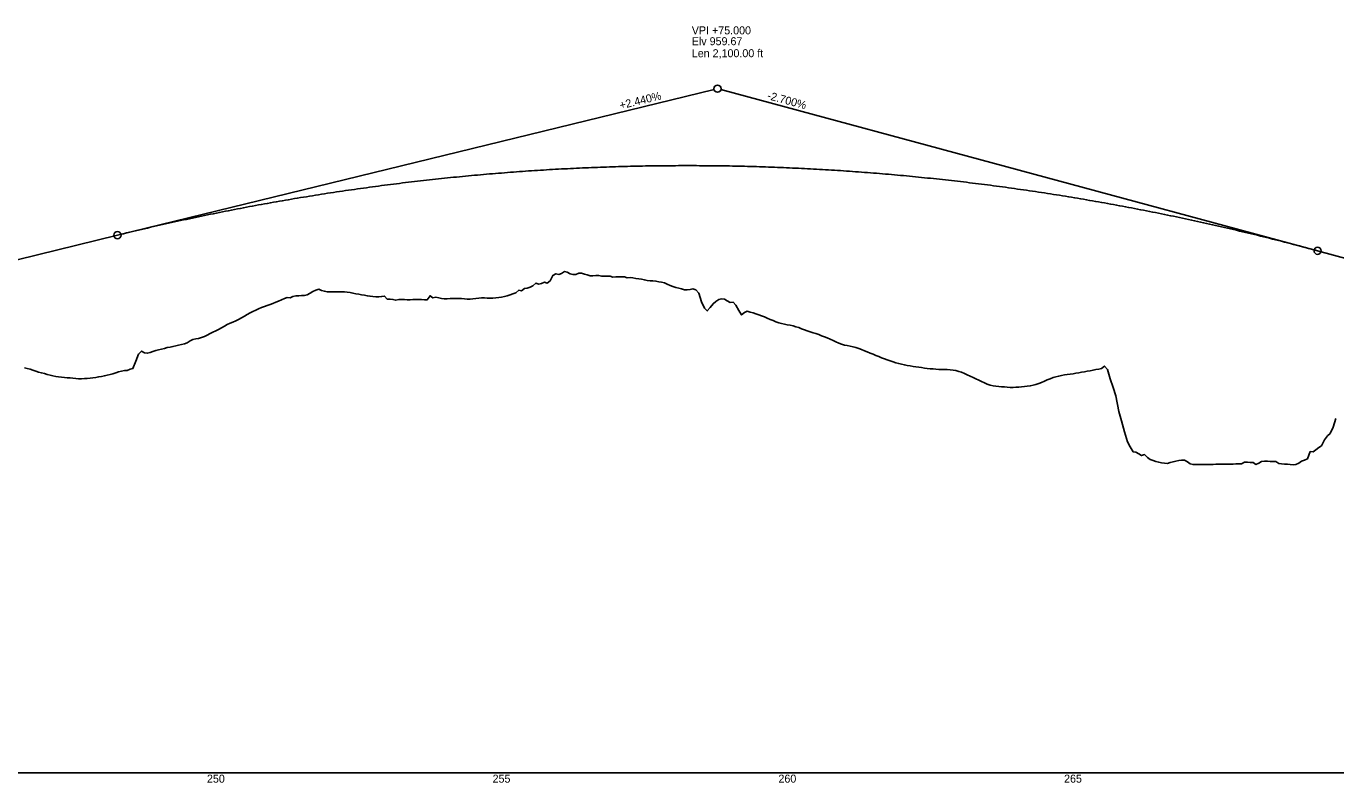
# Model space of a CAD drawing. Extents: x 5180909 to 5237144, y 3695282 to 3720102.
# Drawn here: x 5228426 to 5230717, y 3697765 to 3699088 of the extents above; entities that cross this region are included whole.
import ezdxf

# ---------------------------------------------------------------- set-up
doc = ezdxf.new("R2010")
doc.units = 0
for name, color, linetype in [('dsnEntranceGranular', 7, 'Continuous'), ('dsnShoulderGran', 7, 'Continuous'), ('dsnShoulderPaved', 7, 'Continuous'), ('dsnStgShadingPropGrdLim', 7, 'Continuous'), ('EdgeShoulder', 7, 'Continuous'), ('Entrance', 7, 'Continuous')]:
    doc.layers.add(name, color=color, linetype=linetype)

msp = doc.modelspace()

# ---------------------------------------------------------------- linework, layer by layer
at = {"layer": 'dsnEntranceGranular'}
msp.add_line((5221643.6, 3697782), (5237143.6, 3697782), dxfattribs=at)
at = {"layer": 'dsnShoulderPaved'}
for points in [[(5229142.7, 3698614.1), (5229147.7, 3698613), (5229152.7, 3698611.9), (5229157.7, 3698611), (5229162.7, 3698611.1), (5229167.7, 3698611.4), (5229172.7, 3698611.4), (5229177.7, 3698611.5), (5229182.7, 3698611.8), (5229187.7, 3698611.7), (5229192.7, 3698611.1), (5229197.7, 3698610.7), (5229202.7, 3698610.7), (5229207.7, 3698611.1), (5229212.7, 3698611.7), (5229217.7, 3698612.3), (5229222.7, 3698612.9), (5229227.7, 3698612.7), (5229232.7, 3698612.4), (5229237.7, 3698612.1), (5229242.7, 3698612.2), (5229247.7, 3698612.8), (5229252.7, 3698613.4), (5229257.7, 3698614.1), (5229262.7, 3698615), (5229267.7, 3698616.3), (5229272.7, 3698618), (5229277.7, 3698619.7), (5229282.7, 3698621.4), (5229287.7, 3698626.2), (5229292.7, 3698625.3), (5229297.7, 3698629.4), (5229302.7, 3698629.5), (5229307.7, 3698631.4), (5229312.7, 3698633.6), (5229317.7, 3698638.6), (5229322.7, 3698636.6), (5229327.7, 3698638), (5229332.7, 3698640), (5229337.7, 3698638.4), (5229342.7, 3698642.5), (5229347.7, 3698652), (5229352.7, 3698654.9), (5229357.7, 3698653.8), (5229362.7, 3698655.2), (5229367.7, 3698658.6), (5229372.7, 3698657.6), (5229377.7, 3698654.8), (5229382.7, 3698653.4), (5229387.7, 3698653.9), (5229392.7, 3698655.9), (5229397.7, 3698656.1), (5229402.7, 3698654.3), (5229407.7, 3698652.8), (5229412.7, 3698651.6), (5229417.7, 3698651.3), (5229422.7, 3698651.7), (5229427.7, 3698651.9), (5229432.7, 3698651), (5229437.7, 3698650.9), (5229442.7, 3698650.6), (5229447.7, 3698650.5), (5229452.7, 3698648.9), (5229457.7, 3698649.7), (5229462.7, 3698649.8), (5229467.7, 3698649.3), (5229472.7, 3698649.3), (5229477.7, 3698648.1), (5229482.7, 3698648.2), (5229487.7, 3698647.6), (5229492.7, 3698646.9), (5229497.7, 3698646.3), (5229502.7, 3698645.2), (5229507.7, 3698644.1), (5229512.7, 3698643.3), (5229517.7, 3698642.8), (5229522.7, 3698642.6), (5229527.7, 3698642.1), (5229532.7, 3698641), (5229537.7, 3698640), (5229542.7, 3698638.8), (5229547.7, 3698636.5), (5229552.7, 3698634.3), (5229557.7, 3698632.4), (5229562.7, 3698631.1), (5229567.7, 3698629.7), (5229572.7, 3698628.3), (5229577.7, 3698627.1), (5229582.7, 3698627), (5229587.7, 3698627.7), (5229592.7, 3698628.3), (5229597.7, 3698626.8), (5229602.7, 3698621.2), (5229607.7, 3698606.1), (5229612.7, 3698594.7), (5229617.7, 3698589.9), (5229622.7, 3698595.7), (5229627.7, 3698602.6), (5229632.7, 3698606.6), (5229637.7, 3698610.1), (5229642.7, 3698610.9)], [(5228642.7, 3698517), (5228647.7, 3698518.7), (5228652.7, 3698520.5), (5228657.7, 3698522), (5228662.7, 3698523.3), (5228667.7, 3698524.2), (5228672.7, 3698525.7), (5228677.7, 3698526.6), (5228682.7, 3698527.6), (5228687.7, 3698528.7), (5228692.7, 3698530.2), (5228697.7, 3698531.4), (5228702.7, 3698532.5), (5228707.7, 3698533.9), (5228712.7, 3698537.4), (5228717.7, 3698540.1), (5228722.7, 3698541), (5228727.7, 3698541.6), (5228732.7, 3698543.5), (5228737.7, 3698545.4), (5228742.7, 3698547.8), (5228747.7, 3698550.3), (5228752.7, 3698552.6), (5228757.7, 3698554.9), (5228762.7, 3698557.6), (5228767.7, 3698560.5), (5228772.7, 3698563.3), (5228777.7, 3698566.1), (5228782.7, 3698568.6), (5228787.7, 3698570.5), (5228792.7, 3698572.5), (5228797.7, 3698574.8), (5228802.7, 3698577.6), (5228807.7, 3698580.6), (5228812.7, 3698583.6), (5228817.7, 3698586.5), (5228822.7, 3698588.8), (5228827.7, 3698591.2), (5228832.7, 3698593.5), (5228837.7, 3698595.8), (5228842.7, 3698597.7), (5228847.7, 3698599.4), (5228852.7, 3698601.2), (5228857.7, 3698603), (5228862.7, 3698605), (5228867.7, 3698606.9), (5228872.7, 3698609.2), (5228877.7, 3698611.5), (5228882.7, 3698613.2), (5228887.7, 3698612.9), (5228892.7, 3698615.3), (5228897.7, 3698616.3), (5228902.7, 3698616.5), (5228907.7, 3698616.7), (5228912.7, 3698617.2), (5228917.7, 3698618.2), (5228922.7, 3698621), (5228927.7, 3698623.8), (5228932.7, 3698626.5), (5228937.7, 3698628.1), (5228942.7, 3698625.8), (5228947.7, 3698624.4), (5228952.7, 3698623.4), (5228957.7, 3698623.3), (5228962.7, 3698623.4), (5228967.7, 3698623.5), (5228972.7, 3698623.5), (5228977.7, 3698623.5), (5228982.7, 3698623.3), (5228987.7, 3698622.9), (5228992.7, 3698622.1), (5228997.7, 3698621.1), (5229002.7, 3698620), (5229007.7, 3698619), (5229012.7, 3698617.9), (5229017.7, 3698617.4), (5229022.7, 3698616.6), (5229027.7, 3698615.6), (5229032.7, 3698615.1), (5229037.7, 3698614.8), (5229042.7, 3698614.5), (5229047.7, 3698614.9), (5229052.7, 3698616), (5229057.7, 3698610.4), (5229062.7, 3698610.6), (5229067.7, 3698610.2), (5229072.7, 3698608.5), (5229077.7, 3698609.7), (5229082.7, 3698609.7), (5229087.7, 3698609.7), (5229092.7, 3698609.6), (5229097.7, 3698609.6), (5229102.7, 3698609.7), (5229107.7, 3698609.7), (5229112.7, 3698609.8), (5229117.7, 3698609.8), (5229122.7, 3698609.4), (5229127.7, 3698609.4), (5229132.7, 3698616.5), (5229137.7, 3698613.1), (5229142.7, 3698614.1)], [(5229642.7, 3698610.9), (5229647.7, 3698610.5), (5229652.7, 3698607.4), (5229657.7, 3698604.4), (5229662.7, 3698605.2), (5229667.7, 3698599.9), (5229672.7, 3698590.9), (5229677.7, 3698583), (5229682.7, 3698587.4), (5229687.7, 3698589.3), (5229692.7, 3698587.8), (5229697.7, 3698586.4), (5229702.7, 3698585), (5229707.7, 3698583.1), (5229712.7, 3698581.5), (5229717.7, 3698579.5), (5229722.7, 3698577.4), (5229727.7, 3698575.2), (5229732.7, 3698573.1), (5229737.7, 3698571.1), (5229742.7, 3698569.4), (5229747.7, 3698568.2), (5229752.7, 3698567), (5229757.7, 3698565.9), (5229762.7, 3698564.8), (5229767.7, 3698563.7), (5229772.7, 3698562.3), (5229777.7, 3698560.7), (5229782.7, 3698558.9), (5229787.7, 3698557.1), (5229792.7, 3698555.3), (5229797.7, 3698553.5), (5229802.7, 3698551.8), (5229807.7, 3698550.2), (5229812.7, 3698548.7), (5229817.7, 3698546.6), (5229822.7, 3698544.6), (5229827.7, 3698542.8), (5229832.7, 3698540.5), (5229837.7, 3698538.2), (5229842.7, 3698535.9), (5229847.7, 3698533.8), (5229852.7, 3698532.1), (5229857.7, 3698530.3), (5229862.7, 3698529.3), (5229867.7, 3698528.3), (5229872.7, 3698527), (5229877.7, 3698525.8), (5229882.7, 3698524.1), (5229887.7, 3698522.3), (5229892.7, 3698520.3), (5229897.7, 3698518.2), (5229902.7, 3698516.1), (5229907.7, 3698514.1), (5229912.7, 3698512.1), (5229917.7, 3698510.1), (5229922.7, 3698508), (5229927.7, 3698506.2), (5229932.7, 3698504.4), (5229937.7, 3698502.6), (5229942.7, 3698501), (5229947.7, 3698499.4), (5229952.7, 3698497.9), (5229957.7, 3698496.7), (5229962.7, 3698495.5), (5229967.7, 3698494.6), (5229972.7, 3698493.8), (5229977.7, 3698493), (5229982.7, 3698492.1), (5229987.7, 3698491.5), (5229992.7, 3698490.8), (5229997.7, 3698490.1), (5230002.7, 3698489.4), (5230007.7, 3698488.8), (5230012.7, 3698488.4), (5230017.7, 3698488), (5230022.7, 3698487.6), (5230027.7, 3698487.6), (5230032.7, 3698487.7), (5230037.7, 3698487.5), (5230042.7, 3698487.2), (5230047.7, 3698486.5), (5230052.7, 3698485.6), (5230057.7, 3698484.2), (5230062.7, 3698482.7), (5230067.7, 3698480.8), (5230072.7, 3698478.2), (5230077.7, 3698475.7), (5230082.7, 3698473.3), (5230087.7, 3698471.2), (5230092.7, 3698469), (5230097.7, 3698466.5), (5230102.7, 3698464.2), (5230107.7, 3698461.7), (5230112.7, 3698460.3), (5230117.7, 3698459.1), (5230122.7, 3698458.5), (5230127.7, 3698457.9), (5230132.7, 3698457.4), (5230137.7, 3698457), (5230142.7, 3698456.7)], [(5228422.7, 3698490.4), (5228427.7, 3698489.2), (5228432.7, 3698488), (5228437.7, 3698486.4), (5228442.7, 3698484.8), (5228447.7, 3698483.1), (5228452.7, 3698481.6), (5228457.7, 3698480.3), (5228462.7, 3698478.9), (5228467.7, 3698477.7), (5228472.7, 3698476.5), (5228477.7, 3698475.3), (5228482.7, 3698474.7), (5228487.7, 3698474.2), (5228492.7, 3698473.7), (5228497.7, 3698473.1), (5228502.7, 3698472.7), (5228507.7, 3698472.2), (5228512.7, 3698471.8), (5228517.7, 3698471.3), (5228522.7, 3698471.4), (5228527.7, 3698471.7), (5228532.7, 3698472), (5228537.7, 3698472.3), (5228542.7, 3698472.9), (5228547.7, 3698473.7), (5228552.7, 3698474.5), (5228557.7, 3698475.5), (5228562.7, 3698476.7), (5228567.7, 3698477.8), (5228572.7, 3698478.9), (5228577.7, 3698480.1), (5228582.7, 3698481.7), (5228587.7, 3698483.3), (5228592.7, 3698484.5), (5228597.7, 3698485.7), (5228602.7, 3698485.5), (5228607.7, 3698488.1), (5228612.7, 3698489.2), (5228617.7, 3698501.9), (5228622.7, 3698514.3), (5228627.7, 3698519.7), (5228632.7, 3698516.5), (5228637.7, 3698515.8), (5228642.7, 3698517)], [(5230142.7, 3698456.7), (5230147.7, 3698456.3), (5230152.7, 3698456), (5230157.7, 3698456.4), (5230162.7, 3698456.7), (5230167.7, 3698457.2), (5230172.7, 3698457.7), (5230177.7, 3698458.2), (5230182.7, 3698458.8), (5230187.7, 3698460.1), (5230192.7, 3698461.4), (5230197.7, 3698463), (5230202.7, 3698465), (5230207.7, 3698467.1), (5230212.7, 3698469.2), (5230217.7, 3698471.4), (5230222.7, 3698473.5), (5230227.7, 3698474.8), (5230232.7, 3698476.1), (5230237.7, 3698477.2), (5230242.7, 3698477.9), (5230247.7, 3698478.6), (5230252.7, 3698479.3), (5230257.7, 3698480.1), (5230262.7, 3698481), (5230267.7, 3698481.9), (5230272.7, 3698482.8), (5230277.7, 3698483.6), (5230282.7, 3698484.5), (5230287.7, 3698485.3), (5230292.7, 3698486.5), (5230297.7, 3698487.6), (5230302.7, 3698488.1), (5230307.7, 3698489), (5230312.7, 3698493.6), (5230317.7, 3698487.4), (5230322.7, 3698471), (5230327.7, 3698456), (5230332.7, 3698441.2), (5230337.7, 3698414.1), (5230342.7, 3698397.5), (5230347.7, 3698378.5), (5230352.7, 3698360.8), (5230357.7, 3698352), (5230362.7, 3698343.7), (5230367.7, 3698343.1), (5230372.7, 3698340.2), (5230377.7, 3698336.9), (5230382.7, 3698338.7), (5230387.7, 3698333.9), (5230392.7, 3698330.4), (5230397.7, 3698328.5), (5230402.7, 3698326.8), (5230407.7, 3698325.2), (5230412.7, 3698324.4), (5230417.7, 3698323.7), (5230422.7, 3698323.1), (5230427.7, 3698324.8), (5230432.7, 3698326.1), (5230437.7, 3698327.2), (5230442.7, 3698328.2), (5230447.7, 3698329.1), (5230452.7, 3698329), (5230457.7, 3698326.3), (5230462.7, 3698322.7), (5230467.7, 3698321.1), (5230472.7, 3698321.2), (5230477.7, 3698321.2), (5230482.7, 3698321.3), (5230487.7, 3698321.4), (5230492.7, 3698321.5), (5230497.7, 3698321.6), (5230502.7, 3698321.6), (5230507.7, 3698321.7), (5230512.7, 3698321.8), (5230517.7, 3698321.9), (5230522.7, 3698322), (5230527.7, 3698322), (5230532.7, 3698322.1), (5230537.7, 3698322.2), (5230542.7, 3698322.3), (5230547.7, 3698322.4), (5230552.7, 3698322.4), (5230557.7, 3698325.4), (5230562.7, 3698325.5), (5230567.7, 3698325.1), (5230572.7, 3698324.8), (5230577.7, 3698321.5), (5230582.7, 3698323.5), (5230587.7, 3698326.7), (5230592.7, 3698327.2), (5230597.7, 3698327.1), (5230602.7, 3698326.9), (5230607.7, 3698326.7), (5230612.7, 3698326.5), (5230617.7, 3698322.9), (5230622.7, 3698322.5), (5230627.7, 3698322.1), (5230632.7, 3698321.8), (5230637.7, 3698321.4), (5230642.7, 3698321)], [(5230642.7, 3698321), (5230647.7, 3698321.1), (5230652.7, 3698323.8), (5230657.7, 3698327), (5230662.7, 3698329), (5230667.7, 3698331.4), (5230672.7, 3698344.1), (5230677.7, 3698343.7), (5230682.7, 3698347), (5230687.7, 3698351), (5230692.7, 3698354.2), (5230697.7, 3698364.7), (5230702.7, 3698371.3), (5230707.7, 3698375.6), (5230712.7, 3698386.6), (5230717.7, 3698401.9)]]:
    msp.add_lwpolyline(points, dxfattribs=at)
at = {"layer": 'dsnStgShadingPropGrdLim'}
for p, q in [((5227735.6, 3698515), (5228585.6, 3698722.4)), ((5230685.6, 3698695.1), (5231085.6, 3698587.1))]:
    msp.add_line(p, q, dxfattribs=at)
msp.add_spline([(5228585.6, 3698722.4), (5228627.6, 3698732.5), (5228669.6, 3698742.1), (5228711.6, 3698751.2), (5228753.6, 3698760), (5228795.6, 3698768.3), (5228837.6, 3698776.2), (5228879.6, 3698783.6), (5228921.6, 3698790.6), (5228963.6, 3698797.2), (5229005.6, 3698803.3), (5229047.6, 3698809), (5229089.6, 3698814.3), (5229131.6, 3698819.2), (5229173.6, 3698823.6), (5229215.6, 3698827.6), (5229257.6, 3698831.1), (5229299.6, 3698834.3), (5229341.6, 3698837), (5229383.6, 3698839.2), (5229425.6, 3698841), (5229467.6, 3698842.4), (5229509.6, 3698843.4), (5229551.6, 3698843.9), (5229593.6, 3698844), (5229635.6, 3698843.7), (5229677.6, 3698843), (5229719.6, 3698841.8), (5229761.6, 3698840.1), (5229803.6, 3698838.1), (5229845.6, 3698835.6), (5229887.6, 3698832.7), (5229929.6, 3698829.3), (5229971.6, 3698825.5), (5230013.6, 3698821.3), (5230055.6, 3698816.7), (5230097.6, 3698811.6), (5230139.6, 3698806.1), (5230181.6, 3698800.1), (5230223.6, 3698793.8), (5230265.6, 3698786.9), (5230307.6, 3698779.7), (5230349.6, 3698772), (5230391.6, 3698763.9), (5230433.6, 3698755.4), (5230475.6, 3698746.4), (5230517.6, 3698737), (5230559.6, 3698727.2), (5230601.6, 3698717), (5230643.6, 3698706.3), (5230685.6, 3698695.1)], degree=3, dxfattribs=at)
at = {"layer": 'Entrance'}
for p, q in [((5228585.6, 3698722.4), (5229629.5, 3698977.2)), ((5230685.6, 3698695.1), (5229641.6, 3698977))]:
    msp.add_line(p, q, dxfattribs=at)
for centre in [(5229635.6, 3698978.6), (5228585.6, 3698722.4), (5230685.6, 3698695.1)]:
    msp.add_circle(centre, 6.25, dxfattribs=at)

# ---------------------------------------------------------------- texts
at = {"layer": 'dsnShoulderGran'}
for s, p in [('250', (5228742.2, 3697765)), ('255', (5229242, 3697765)), ('260', (5229742.2, 3697765)), ('265', (5230242, 3697765))]:
    msp.add_text(s, height=14, dxfattribs=at).set_placement(p)
at = {"layer": 'EdgeShoulder'}
for s, p in [('VPI +75.000', (5229590.6, 3699073.6)), ('Elv 959.67', (5229590.6, 3699054.6)), ('Len 2,100.00 ft', (5229590.6, 3699033.6))]:
    msp.add_text(s, height=14, dxfattribs=at).set_placement(p)
for s, rotation, p in [('+2.440%', 13.7122, (5229466, 3698942.4)), ('-2.700%', 344.8904, (5229721.6, 3698960.6))]:
    msp.add_text(s, height=14, rotation=rotation, dxfattribs=at).set_placement(p)

doc.saveas('drawing.dxf')
